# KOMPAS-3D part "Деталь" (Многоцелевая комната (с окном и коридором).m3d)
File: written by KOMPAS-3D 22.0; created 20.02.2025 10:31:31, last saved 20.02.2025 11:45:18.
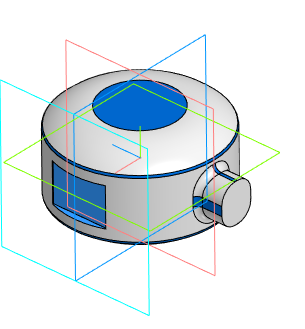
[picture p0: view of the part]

Document properties: Автор: Пользователь Windows; Полное имя файла: C:\Users\Student\Documents\Картошечка\База Сабнатика\Многоцелевая комната\Многоцелевая комната (с окном и коридором).m3d

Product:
- Part/product: Деталь
    Масса: 0.425402

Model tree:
1. Эскиз:3
2. Элемент вращения:1
     Угол 1 = 360
3. Скругление:1  (with: Элемент вращения:1)
     Радиус = 1
4. Смещенная плоскость:1
     Расстояние = 25
5. Эскиз:4
6. Элемент выдавливания:1
     Расстояние 2 = 2
7. Эскиз:5
8. Элемент выдавливания:2
     Расстояние 1 = 32.5
9. Скругление:3  (with: Элемент выдавливания:2)
     Радиус = 2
